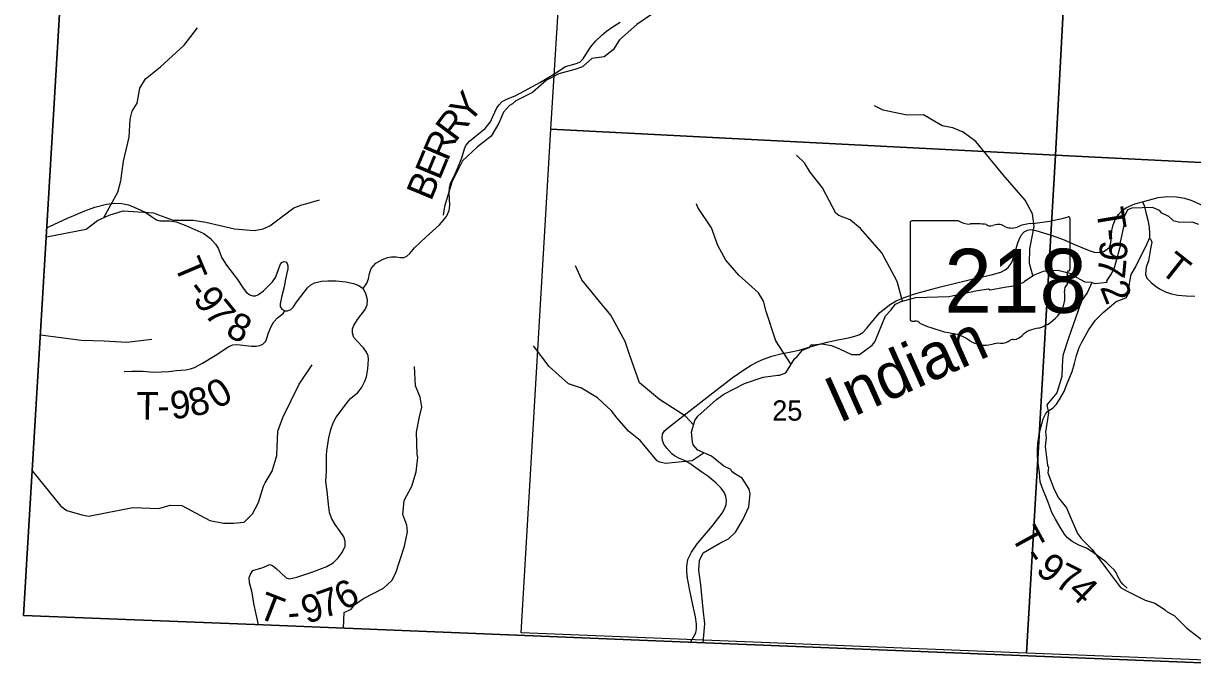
# Model space of a CAD drawing. Extents: x 1878108 to 2183446, y 146837 to 508383.
# Drawn here: x 2008020 to 2020751, y 212550 to 219622 of the extents above; entities that cross this region are included whole.
import ezdxf

# ---------------------------------------------------------------- set-up
doc = ezdxf.new("R2010")
doc.units = 0
for name, color, linetype in [('GM_X_Adjacent_County', 7, 'Continuous'), ('GM_X_County', 7, 'Continuous'), ('GM_X_Minor_River', 7, 'Continuous'), ('GM_X_Minor_River_Text', 7, 'Continuous'), ('GM_X_Section', 7, 'Continuous'), ('GM_X_Section_Text', 7, 'Continuous'), ('GM_X_State_Location', 7, 'Continuous'), ('GM_X_State_Route', 7, 'Continuous'), ('GM_X_State_Shield', 7, 'Continuous'), ('GM_X_Township', 7, 'Continuous'), ('GM_X_Township_Road', 7, 'Continuous'), ('GM_X_Township_Road_Text', 7, 'Continuous'), ('GM_X_Township_ROW', 7, 'Continuous')]:
    doc.layers.add(name, color=color, linetype=linetype)

msp = doc.modelspace()

# ---------------------------------------------------------------- linework, layer by layer
at = {"layer": 'GM_X_Adjacent_County'}
msp.add_lwpolyline([(2009016, 229762), (2008888, 227673), (2008870, 227386), (2008698, 224504), (2008642, 223563), (2008270, 217353), (2008056, 213785), (2008020, 213174), (2010538, 213073), (2015261, 212882), (2022114, 212606)], dxfattribs=at)
at = {"layer": 'GM_X_County'}
msp.add_lwpolyline([(2022114, 212606), (2015261, 212882), (2010538, 213073), (2008020, 213174), (2008056, 213785), (2008270, 217353), (2008642, 223563), (2008698, 224504), (2008870, 227386), (2008888, 227673), (2009016, 229762)], dxfattribs=at)
at = {"layer": 'GM_X_Minor_River'}
for points in [[(2014869, 219725), (2014700, 219610), (2014511, 219443), (2014440, 219335), (2014342, 219256), (2014208, 219241), (2014109, 219149), (2014024, 219118), (2013849, 219074), (2013717, 219002), (2013562, 218868), (2013381, 218780), (2013346, 218747), (2013314, 218726), (2013246, 218656), (2013196, 218537), (2013112, 218395), (2012963, 218276), (2012801, 218125), (2012686, 217892), (2012604, 217628), (2012589, 217534)], [(2008894, 217506), (2009048, 217782), (2009082, 217907), (2009110, 218121), (2009172, 218383), (2009182, 218579), (2009205, 218665), (2009259, 218753), (2009286, 218915), (2009349, 219017), (2009511, 219148), (2009769, 219386), (2009915, 219572)], [(2019011, 216875), (2018973, 217005), (2018978, 217167), (2019027, 217408), (2019009, 217547), (2018928, 217698), (2018687, 217972), (2018389, 218334), (2018252, 218439), (2018140, 218485), (2018025, 218508), (2017819, 218625), (2017639, 218623), (2017383, 218677), (2017287, 218724)], [(2017590, 216597), (2017532, 216811), (2017366, 217123), (2017134, 217389), (2017021, 217483), (2016897, 217531), (2016866, 217556), (2016721, 217832), (2016586, 218002), (2016523, 218102), (2016438, 218187)], [(2008270, 217296), (2008703, 217380), (2008827, 217476), (2008955, 217534), (2009106, 217579), (2009435, 217559), (2009492, 217537), (2009650, 217478), (2009867, 217477), (2010006, 217456), (2010317, 217384), (2010534, 217367), (2010629, 217384), (2010704, 217418), (2010965, 217612), (2011052, 217647), (2011096, 217656), (2011245, 217701)], [(2015422, 212876), (2015441, 213083), (2015423, 213240), (2015397, 213507), (2015373, 213667), (2015383, 213770), (2015420, 213856), (2015602, 213961), (2015696, 214009), (2015772, 214081), (2015855, 214214), (2015917, 214357), (2015933, 214499), (2015923, 214549), (2015847, 214668), (2015755, 214722), (2015733, 214740), (2015723, 214762), (2015647, 214800), (2015513, 214908), (2015363, 214974), (2015312, 215030), (2015306, 215064), (2015293, 215170), (2015329, 215295), (2015365, 215343), (2015567, 215526), (2015646, 215584), (2015870, 215699), (2016073, 215768), (2016235, 215790), (2016253, 215792), (2016323, 215815), (2016414, 215967), (2016444, 215993), (2016504, 216062), (2016584, 216096), (2016592, 216122), (2016614, 216120), (2016714, 216131), (2016819, 216115), (2016907, 216077), (2017035, 216015), (2017125, 216017), (2017263, 216116), (2017290, 216152), (2017294, 216162), (2017408, 216437), (2017464, 216498), (2017516, 216562), (2017579, 216594), (2017737, 216637), (2018098, 216648), (2018408, 216712), (2018527, 216731), (2018547, 216719), (2018701, 216749), (2018873, 216774), (2018871, 216786), (2018913, 216802), (2018917, 216812), (2019018, 216878), (2019126, 216923), (2019282, 216935), (2019386, 216907), (2019457, 216890), (2019481, 216858), (2019577, 216806), (2019647, 216802), (2019685, 216790), (2019819, 216804), (2019815, 216818), (2019869, 216895), (2019904, 216975), (2019968, 217214), (2019964, 217238), (2020006, 217419), (2020010, 217517), (2020044, 217595), (2020091, 217614), (2020309, 217620), (2020387, 217586), (2020403, 217562), (2020489, 217522), (2020539, 217476), (2020611, 217456), (2020742, 217459), (2020814, 217435)], [(2016378, 215905), (2016212, 216165), (2016106, 216483), (2016077, 216596), (2016024, 216688), (2015810, 216878), (2015667, 217043), (2015580, 217202), (2015513, 217396), (2015364, 217618), (2015348, 217657)], [(2015316, 215249), (2015229, 215343), (2014945, 215526), (2014727, 215706), (2014619, 216014), (2014573, 216158), (2014416, 216443), (2014293, 216593), (2014101, 216830), (2014031, 216981)], [(2019654, 216800), (2019607, 216695), (2019539, 216599), (2019504, 216494), (2019400, 216195), (2019336, 216006), (2019329, 215888), (2019327, 215776), (2019271, 215599), (2019165, 215468), (2019181, 215380), (2019148, 215171), (2019156, 215111), (2019146, 215013), (2019170, 214810), (2019180, 214786), (2019176, 214728), (2019244, 214545), (2019290, 214455), (2019376, 214347), (2019406, 214277), (2019498, 214064), (2019542, 214006), (2019658, 213890), (2019814, 213682), (2019964, 213479), (2020039, 213437), (2020235, 213339), (2020339, 213308), (2020451, 213234), (2020473, 213214), (2020551, 213172), (2020689, 213033), (2020922, 212853)], [(2008207, 216230), (2008648, 216171), (2008899, 216163), (2009146, 216149), (2009419, 216184)], [(2015431, 214944), (2015300, 214859), (2015012, 214828), (2014948, 214844), (2014921, 214857), (2014736, 215078), (2014609, 215180), (2014484, 215322), (2014422, 215401), (2014271, 215542), (2014097, 215648), (2013956, 215696), (2013743, 215885), (2013574, 216109)], [(2008118, 214744), (2008426, 214364), (2008494, 214315), (2008656, 214270), (2008728, 214256), (2009211, 214350), (2009493, 214337), (2009617, 214375), (2009745, 214371), (2010049, 214209), (2010198, 214180), (2010306, 214177), (2010424, 214189), (2010515, 214279), (2010578, 214403), (2010633, 214580), (2010651, 214617), (2010728, 214745), (2010781, 214916), (2010789, 215182), (2010846, 215331), (2011023, 215694), (2011163, 215902)], [(2011506, 213034), (2011513, 213205), (2011587, 213241), (2011629, 213293), (2011724, 213356), (2011940, 213469), (2012032, 213553), (2012075, 213638), (2012171, 213927), (2012201, 214083), (2012193, 214158), (2012151, 214274), (2012166, 214425), (2012250, 214583), (2012296, 214736), (2012314, 214894), (2012308, 214927), (2012301, 215171), (2012333, 215336), (2012357, 215442), (2012339, 215549), (2012289, 215675), (2012277, 215886)]]:
    msp.add_lwpolyline(points, dxfattribs=at)
at = {"layer": 'GM_X_Section'}
for points in [[(2016994, 223794), (2019561, 223713), (2019576, 223712), (2019514, 222706), (2019378, 220437), (2019257, 218185), (2013761, 218471), (2014100, 223898)], [(2024807, 220146), (2024671, 217914), (2019257, 218185), (2019378, 220437)], [(2013761, 218471), (2019257, 218185), (2018943, 212762), (2013441, 212985)], [(2019257, 218185), (2024671, 217914), (2024595, 216697), (2024559, 216127), (2024520, 215496), (2024482, 214858), (2024442, 214172), (2024399, 213435), (2024345, 212550), (2018943, 212762)]]:
    msp.add_lwpolyline(points, close=True, dxfattribs=at)
at = {"layer": 'GM_X_State_Route'}
msp.add_lwpolyline([(2015283, 212882), (2015340, 212982), (2015350, 213027), (2015349, 213079), (2015337, 213158), (2015308, 213288), (2015272, 213464), (2015251, 213580), (2015244, 213649), (2015244, 213711), (2015254, 213781), (2015293, 213864), (2015356, 213952), (2015520, 214146), (2015630, 214288), (2015657, 214342), (2015670, 214382), (2015674, 214427), (2015668, 214470), (2015653, 214510), (2015616, 214559), (2015560, 214617), (2015473, 214689), (2015408, 214734), (2015331, 214787), (2015277, 214830), (2015219, 214861), (2015162, 214882), (2015111, 214910), (2015080, 214935), (2015024, 214995), (2014993, 215038), (2014977, 215077), (2014974, 215111), (2014978, 215148), (2015002, 215184), (2015048, 215225), (2015233, 215369), (2015559, 215624), (2015738, 215760), (2015875, 215857), (2015943, 215900), (2016019, 215939), (2016079, 215966), (2016168, 215997), (2016283, 216025), (2016360, 216040), (2016466, 216064), (2016624, 216110), (2016773, 216149), (2016888, 216177), (2017003, 216196), (2017073, 216215), (2017118, 216228), (2017159, 216256), (2017204, 216303), (2017269, 216384), (2017346, 216472), (2017410, 216525), (2017449, 216557), (2017522, 216601), (2017610, 216638), (2017738, 216681), (2018006, 216753), (2018302, 216824), (2018573, 216886), (2018662, 216914), (2018711, 216937), (2018744, 216963), (2018774, 217007), (2018789, 217039), (2018800, 217071), (2018848, 217232), (2018869, 217287), (2018887, 217319), (2018918, 217351), (2018954, 217371), (2018989, 217376), (2019043, 217366), (2019210, 217314), (2019353, 217264), (2019466, 217215), (2019624, 217149), (2019680, 217131), (2019735, 217125), (2019782, 217137), (2019818, 217161), (2019845, 217186), (2019856, 217218), (2019865, 217259), (2019872, 217365), (2019886, 217428), (2019909, 217484), (2019943, 217539), (2019975, 217576), (2020030, 217616), (2020123, 217658), (2020206, 217680), (2020376, 217724), (2020476, 217736), (2020576, 217734), (2020662, 217720), (2020743, 217693), (2020845, 217644)], dxfattribs=at)
at = {"layer": 'GM_X_State_Shield'}
for p, q in [((2017676, 217453), (2017676, 216396)), ((2018202, 217471), (2017693, 217471)), ((2019416, 216944), (2019416, 217497)), ((2019416, 216944), (2019416, 216944))]:
    msp.add_line(p, q, dxfattribs=at)
for centre, major_axis, start_param, end_param in [((2017696, 217455), (20.2, 0), 1.712693, 3.28349), ((2018324, 217593), (196, 0), 4.042523, 4.731795), ((2018796, 218911), (1845, 0), 4.814394, 5.042369), ((2019397, 217499), (19.4, 0), 6.141152, 7.989035), ((2018389, 216878), (702, 0), 1.404758, 1.657858), ((2018548, 217460), (56.4, 0), 3.836095, 5.185415), ((2018631, 217338), (117, 0), 0.950623, 2.079405), ((2018782, 217506), (141, 0), 4.081561, 5.145723), ((2019031, 217148), (371, 0), 1.699011, 2.107814), ((2019395, 216942), (20.7, 0), 5.05454, 6.418171), ((2019411, 216904), (30, 0), 1.883978, 3.671073), ((2019221, 216834), (180, 0), 5.934695, 6.695948), ((2018899, 216643), (462, 0), 5.101752, 6.440018), ((2019485, 216713), (131, 0), 2.387724, 3.262537), ((2017696, 216394), (20.3, 0), 3.00124, 4.508301), ((2017699, 216502), (155, 0), 4.665946, 4.897461), ((2017731, 216335), (56, 0), 0.519207, 1.627899), ((2018437, 217284), (1333, 0), 4.195997, 4.488961), ((2018040, 215921), (417, 0), 0.823519, 1.323587), ((2018791, 216148), (39.7, 0), 1.147584, 2.315152), ((2018774, 216294), (149, 0), 4.937069, 5.64225), ((2019094, 216099), (253, 0), 1.647645, 2.488434), ((2018491, 216330), (265, 0), 4.026481, 4.996735), ((2018644, 215964), (217, 0), 1.495662, 1.94098), ((2018663, 216251), (141, 0), 4.691044, 5.507374)]:
    msp.add_ellipse(centre, major_axis=major_axis, ratio=0.8, start_param=start_param, end_param=end_param, dxfattribs=at)
at = {"layer": 'GM_X_Township'}
msp.add_lwpolyline([(2022114, 212606), (2015261, 212882), (2010538, 213073), (2008020, 213174), (2008056, 213785), (2008270, 217353), (2008642, 223563), (2008698, 224504), (2008870, 227386), (2008888, 227673), (2009016, 229762)], dxfattribs=at)
at = {"layer": 'GM_X_Township_Road'}
for points in [[(2011721, 216736), (2011758, 216794), (2011778, 216841), (2011790, 216896), (2011808, 216954), (2011857, 217009), (2011922, 217047), (2011985, 217073), (2012028, 217079), (2012078, 217079), (2012127, 217073), (2012163, 217072), (2012194, 217087), (2012226, 217117), (2012279, 217177), (2012400, 217293), (2012551, 217428), (2012627, 217517), (2012655, 217585), (2012663, 217641), (2012657, 217778), (2012659, 217835), (2012675, 217889), (2012710, 217958), (2012747, 218042), (2012794, 218157), (2012822, 218257), (2012838, 218292), (2012876, 218341), (2012958, 218404), (2013048, 218477), (2013104, 218549), (2013130, 218608), (2013175, 218701), (2013200, 218736), (2013233, 218770), (2013292, 218800), (2013374, 218832), (2013476, 218888), (2013650, 218982), (2013797, 219070), (2013922, 219151), (2014027, 219180), (2014077, 219200), (2014114, 219236), (2014162, 219312), (2014199, 219367), (2014253, 219431), (2014319, 219494), (2014369, 219537), (2014431, 219580), (2014518, 219636)], [(2008270, 217396), (2008352, 217431), (2008499, 217500), (2008687, 217581), (2008799, 217620), (2008925, 217654), (2009011, 217664), (2009090, 217662), (2009163, 217646), (2009259, 217607), (2009347, 217567), (2009414, 217518), (2009468, 217481), (2009507, 217470), (2009610, 217473), (2009683, 217461), (2009788, 217422), (2009986, 217333), (2010057, 217278), (2010112, 217219), (2010140, 217174), (2010180, 217069), (2010232, 216989), (2010351, 216834), (2010406, 216748), (2010447, 216696), (2010486, 216666), (2010518, 216655), (2010547, 216656), (2010580, 216668), (2010635, 216709), (2010732, 216808), (2010766, 216854), (2010782, 216902), (2010806, 216963), (2010820, 217000), (2010835, 217019), (2010856, 217029), (2010876, 217024), (2010892, 217007), (2010899, 216981), (2010898, 216948), (2010884, 216887), (2010875, 216836), (2010858, 216751), (2010834, 216653), (2010822, 216603), (2010816, 216567), (2010817, 216539), (2010832, 216509), (2010866, 216490), (2010896, 216491), (2010930, 216506), (2010962, 216535), (2010995, 216584), (2011042, 216647), (2011114, 216741), (2011148, 216773), (2011191, 216795), (2011266, 216813), (2011335, 216819), (2011424, 216819), (2011530, 216808), (2011615, 216790), (2011672, 216766), (2011721, 216736)], [(2020206, 217680), (2020222, 217637), (2020240, 217562), (2020263, 217478), (2020278, 217403), (2020280, 217342), (2020283, 217284), (2020297, 217268), (2020305, 217240), (2020292, 217168), (2020271, 217037), (2020246, 216966), (2020239, 216890), (2020253, 216848), (2020300, 216800), (2020342, 216763), (2020389, 216732), (2020454, 216699), (2020522, 216676), (2020591, 216660), (2020679, 216653), (2020775, 216652)], [(2020037, 213470), (2019994, 213510), (2019968, 213541), (2019937, 213599), (2019920, 213640), (2019896, 213671), (2019857, 213708), (2019804, 213756), (2019658, 213866), (2019597, 213907), (2019511, 213940), (2019439, 213977), (2019387, 214019), (2019354, 214060), (2019321, 214116), (2019257, 214222), (2019219, 214295), (2019180, 214397), (2019111, 214567), (2019092, 214630), (2019082, 214732), (2019068, 214832), (2019063, 214905), (2019062, 214970), (2019067, 215047), (2019085, 215165), (2019124, 215313), (2019148, 215365), (2019172, 215395), (2019232, 215436), (2019270, 215476), (2019300, 215527), (2019352, 215613), (2019379, 215680), (2019439, 215832), (2019466, 215918), (2019486, 216005), (2019517, 216091), (2019544, 216151), (2019616, 216282), (2019690, 216387), (2019778, 216472), (2019869, 216550), (2019919, 216591), (2019988, 216618), (2020029, 216635), (2020046, 216669), (2020055, 216725), (2020066, 216810), (2020080, 216888), (2020127, 216967), (2020256, 217223), (2020283, 217284)], [(2010515, 213397), (2010508, 213439), (2010482, 213530), (2010477, 213584), (2010493, 213624), (2010517, 213662), (2010617, 213690), (2010663, 213711), (2010700, 213727), (2010731, 213716), (2010772, 213684), (2010822, 213638), (2010880, 213583), (2010917, 213573), (2010996, 213589), (2011171, 213649), (2011325, 213705), (2011393, 213746), (2011447, 213801), (2011490, 213859), (2011524, 213928), (2011525, 213982), (2011509, 214030), (2011460, 214098), (2011414, 214162), (2011373, 214232), (2011354, 214294), (2011341, 214383), (2011333, 214459), (2011326, 214527), (2011314, 214631), (2011319, 214740), (2011321, 214835), (2011320, 214914), (2011324, 214967), (2011346, 215106), (2011368, 215198), (2011392, 215271), (2011424, 215332), (2011505, 215438), (2011544, 215494), (2011582, 215538), (2011661, 215603), (2011702, 215653), (2011739, 215726), (2011754, 215771), (2011769, 215858), (2011776, 215960), (2011774, 216000), (2011756, 216041), (2011722, 216089), (2011646, 216169), (2011617, 216202), (2011602, 216247), (2011604, 216294), (2011618, 216333), (2011658, 216396), (2011741, 216505), (2011763, 216558), (2011766, 216611), (2011750, 216681), (2011721, 216736)], [(2009118, 215829), (2009200, 215834), (2009323, 215833), (2009432, 215824), (2009518, 215825), (2009603, 215829), (2009686, 215842), (2009789, 215850), (2009839, 215858), (2009883, 215873), (2009968, 215921), (2010107, 216004), (2010169, 216045), (2010228, 216084), (2010263, 216107), (2010299, 216119), (2010337, 216123), (2010379, 216121), (2010439, 216115), (2010505, 216107), (2010554, 216105), (2010594, 216112), (2010627, 216127), (2010658, 216159), (2010670, 216195), (2010689, 216250), (2010718, 216322), (2010747, 216373), (2010786, 216415), (2010849, 216462), (2010866, 216490)]]:
    msp.add_lwpolyline(points, dxfattribs=at)
at = {"layer": 'GM_X_Township_ROW'}
msp.add_lwpolyline([(2010580, 213072), (2010529, 213305), (2010515, 213397)], dxfattribs=at)

# ---------------------------------------------------------------- texts
at = {"layer": 'GM_X_Minor_River_Text'}
msp.add_text('Indian', height=500, rotation=24.1322, dxfattribs=at).set_placement((2016899, 215263))
at = {"layer": 'GM_X_Section_Text'}
msp.add_text('25', height=221, rotation=0, dxfattribs=at).set_placement((2016173, 215295))
at = {"layer": 'GM_X_State_Location'}
for s in ['s', 'r']:
    msp.add_text(s, height=1, dxfattribs=at).set_placement((2018526, 216854))
msp.add_text('218', height=1, rotation=0, dxfattribs=at).set_placement((2018173, 216781))
at = {"layer": 'GM_X_State_Shield'}
msp.add_text('218', height=696.1, dxfattribs=at).set_placement((2018047, 216470))
at = {"layer": 'GM_X_Township_Road_Text'}
for s, rotation, p in [('Y', 50.5662, (2012871, 218516)), ('R', 53.1762, (2012725, 218321)), ('R', 66.8703, (2012638, 218111)), ('E', 67.4314, (2012552, 217905)), ('B', 67.4379, (2012458, 217677)), ('T', 279.4324, (2019698, 217591)), ('-', 274.7672, (2019734, 217377)), ('9', 267.0533, (2019744, 217264)), ('T', 293.1361, (2009656, 216992)), ('T', 321.6934, (2020380, 216919)), ('7', 264.7365, (2019734, 217083)), ('2', 291.7052, (2019739, 216748)), ('-', 307.3145, (2009785, 216716)), ('9', 306.2449, (2009859, 216619)), ('7', 309.5079, (2009979, 216455)), ('8', 334.1447, (2010207, 216226)), ('0', 30.6884, (2010130, 215413)), ('T', 359.1878, (2009246, 215309)), ('9', 6.2676, (2009634, 215310)), ('8', 12.2207, (2009852, 215336)), ('-', 1.2116, (2009482, 215306)), ('T', 298.645, (2018767, 214042)), ('-', 305.2595, (2018895, 213813)), ('9', 321.4887, (2019029, 213646)), ('7', 333.6828, (2019232, 213493)), ('6', 28.1294, (2011506, 213220)), ('4', 316.5071, (2019379, 213425)), ('T', 338.6976, (2010551, 213157)), ('9', 18.0239, (2011103, 213079)), ('7', 19.283, (2011286, 213139)), ('-', 4.9215, (2010907, 213054))]:
    msp.add_text(s, height=300, rotation=rotation, dxfattribs=at).set_placement(p)

doc.saveas('drawing.dxf')
